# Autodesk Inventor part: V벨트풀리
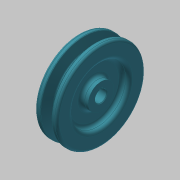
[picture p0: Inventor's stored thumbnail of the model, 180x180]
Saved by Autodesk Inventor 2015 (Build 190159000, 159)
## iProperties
Created: 2015-11
Part Number: V벨트풀리
Material: 강철, 탄소
Document SubType Name: Modeling
Designer: mduedu
Density: 1 g/cm^3
Appearance: 커뎃 파란색
Author: mduedu
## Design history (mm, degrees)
sketch "스케치1"
  geometry: L1 (-9.5, 0)-(9.5, 0); L2 (0, 0)-(0, 37.7); L3 (-4.825, 37.7)-(-9.5, 37.7); L4 (-9.5, 37.7)-(-9.5, 0); L5 (0, 28.7)-(-2.074, 28.7); L6 (-2.074, 28.7)-(-4.825, 37.7); L7 (4.825, 37.7)-(9.5, 37.7); L8 (9.5, 37.7)-(9.5, 0); L9 (0, 28.7)-(2.074, 28.7); L10 (2.074, 28.7)-(4.825, 37.7); L11 (-9.5, 35)-(9.5, 35); 3 further points
  constraints: 22 end point, 7 point on line, 4 perpendicular, 3 symmetric about line, 1 coincident, 1 horizontal, 1 horizontal alignment, 1 midpoint, 1 vertical
  dimensions: "d0" = 19 distance of L1.start L1.end; "d2" = 75.4 diameter of L2.end L1 (derived); "d3" = 34 deg angle of L10 L6; "d4" = 6.3 distance between parallel lines of L11 L9; "d5" = 2.7 distance between parallel lines of L7 L11; "d6" = 8 distance of point (4, 35) point (-4, 35); "d7" = 70 diameter of L11 L1
revolve "회전1" sketch "스케치1" stored, may be unused: angle "d8" = 90 deg
sketch "스케치2"
  geometry: C1 r 24 at (0, 0); C2 r 11 at (0, 0); 1 further point
  constraints: 2 centre point, 2 coincident
  dimensions: "d9" = 48 diameter of C1; "d10" = 22 diameter of C2
extrude "돌출1" cut sketch "스케치2" distance "d11" = 6; taper "d12" = 0 deg
fillet "모깎기1" dims "d13" = 3
fillet "모깎기2" dims "d14" = 3
fillet "모깎기3" dims "d15" = 1, "d16" = 0.5, "d17" = 2
hole "구멍1" diameter "d20" = 10; stored, may be unused: countersink angle "d24" = 90 deg, drill point angle "d26" = 118 deg; dims "d18" = 10, "d19" = 10, "d21" = 6, "d22" = 4, "d23" = 2, "d25" = 8
sketch "스케치3"
  geometry: L1 (-1.5, 0)-(1.5, 0); L2 (1.5, 0)-(1.5, 6.4); L3 (1.5, 6.4)-(-1.5, 6.4); L4 (-1.5, 6.4)-(-1.5, 0); 2 further points
  constraints: 8 end point, 2 parallel, 1 coincident, 1 horizontal, 1 midpoint, 1 perpendicular
  dimensions: "d27" = 3 distance of L2.end L3.end; "d29" = 6.4 distance of L3.end L1.start
extrude "돌출2" cut sketch "스케치3" stored distance "d30" = 6; taper "d31" = 0 deg
chamfer "모따기1" distance "d32" = 0.5; stored, may be unused: second distance "d33" = 2, angle "d34" = 45 deg
node "솔리드1"
mirror "대칭1"
